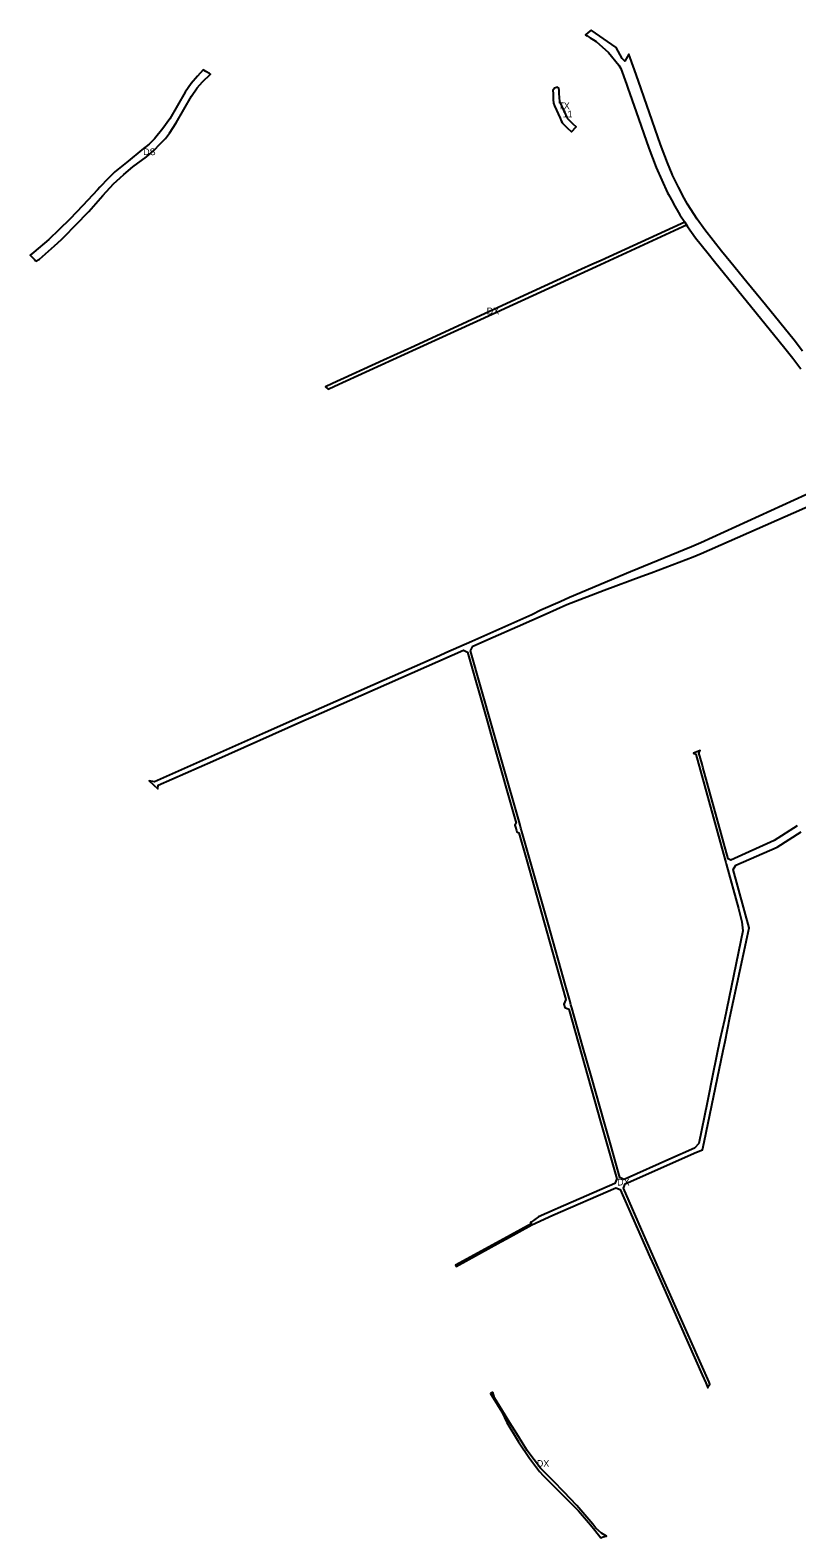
# Model space of a CAD drawing. Extents: x -521882 to -518995, y -1142400 to -1140153.
# Drawn here: x -521882 to -520739, y -1142400 to -1140153 of the extents above; entities that cross this region are included whole.
import ezdxf

# ---------------------------------------------------------------- set-up
doc = ezdxf.new("R2010")
doc.units = 0
for name, color, linetype in [('90320013', 7, 'Continuous'), ('90370013', 7, 'Continuous'), ('90440023', 7, 'Continuous'), ('ID_navrh', 7, 'Continuous')]:
    doc.layers.add(name, color=color, linetype=linetype)

msp = doc.modelspace()

# ---------------------------------------------------------------- linework, layer by layer
at = {"layer": '90320013'}
msp.add_lwpolyline([(-520730.64, -1140631.58), (-520743.28, -1140615.01), (-520785.9, -1140562.81), (-520813.81, -1140528.62), (-520837.71, -1140499.35), (-520851.49, -1140482.48), (-520876.46, -1140450.75), (-520887.82, -1140434.78), (-520902.19, -1140412.67), (-520907.24, -1140403.74), (-520915.77, -1140387.04), (-520924.44, -1140369.44), (-520925.04, -1140368.05), (-520932.27, -1140351.12), (-520942.5, -1140323.7), (-520963.03, -1140264.99), (-520975.5, -1140229.32), (-520981.4, -1140212.45), (-520989.57, -1140189.1), (-520995.82, -1140199.62), (-520997.26, -1140198.03), (-520999.73, -1140195.29), (-521008.55, -1140178.79), (-521045.99, -1140153.16), (-521047.4, -1140154.12), (-521048.05, -1140154.68), (-521053.72, -1140159.58), (-521054.36, -1140160.13), (-521051.86, -1140161.45), (-521047.19, -1140164.44), (-521042.52, -1140167.42), (-521038.45, -1140170.03), (-521019.82, -1140186.27), (-521004.56, -1140205.45), (-521002.93, -1140207.73), (-521001.72, -1140210.08), (-520993.36, -1140233.77), (-520991.34, -1140239.5), (-520978.89, -1140274.79), (-520959.74, -1140329.07), (-520948.85, -1140357.77), (-520931.92, -1140395.43), (-520930.52, -1140398.04), (-520924.28, -1140409.64), (-520923.06, -1140411.9), (-520913.58, -1140428.33), (-520906.37, -1140439.12), (-520903.84, -1140443.54), (-520902.4, -1140445.74), (-520890.58, -1140462.46), (-520871.65, -1140486.28), (-520862.22, -1140497.87), (-520765.71, -1140616.57), (-520757.18, -1140627.06), (-520745.42, -1140642.26), (-520733.42, -1140657.97)], dxfattribs=at)
msp.add_lwpolyline([(-521873.47, -1140497.6), (-521868.24, -1140494.75), (-521845.84, -1140474.71), (-521835.62, -1140465.09), (-521829.77, -1140459.58), (-521815.4, -1140444.86), (-521814.39, -1140443.83), (-521794.87, -1140423.48), (-521773.82, -1140399.6), (-521757.78, -1140381.98), (-521747.91, -1140373.33), (-521742.3, -1140368.5), (-521728.93, -1140357.06), (-521708.67, -1140341.98), (-521697.12, -1140332.11), (-521688.85, -1140323.27), (-521680.22, -1140314.66), (-521674.58, -1140306.67), (-521664.44, -1140291.34), (-521641.46, -1140251.62), (-521633.25, -1140239.25), (-521625.36, -1140230.13), (-521613.09, -1140218.9), (-521614.87, -1140217.86), (-521620.19, -1140214.77), (-521624.31, -1140212.38), (-521632.85, -1140221.77), (-521642.31, -1140232.52), (-521651.12, -1140245.38), (-521673.96, -1140285.19), (-521684.15, -1140299.89), (-521696.71, -1140315.1), (-521704.79, -1140323.18), (-521715.5, -1140331.4), (-521736.25, -1140348.4), (-521755.99, -1140364.38), (-521765.79, -1140374.26), (-521778.1, -1140387.34), (-521781.95, -1140390.97), (-521803.88, -1140414.74), (-521822.79, -1140434.86), (-521839, -1140450.48), (-521854.3, -1140465.27), (-521876.66, -1140484.09), (-521882.18, -1140488.56), (-521879.74, -1140491.09), (-521875.9, -1140495.08)], close=True, dxfattribs=at)
at = {"layer": '90370013'}
for points in [[(-520909.31, -1140446.06), (-520903.84, -1140443.54), (-520906.37, -1140439.12), (-520911.89, -1140441.66), (-521031.07, -1140496.4), (-521045.09, -1140502.65), (-521060.49, -1140509.3), (-521152, -1140551.52), (-521309.07, -1140623.96), (-521355.48, -1140644.9), (-521431.42, -1140679.77), (-521441.99, -1140684.63), (-521438.02, -1140688.47), (-521428.47, -1140683.93), (-521306.81, -1140628.37), (-521187.8, -1140573.75), (-521174.07, -1140567.72), (-521038.29, -1140505.39), (-520909.31, -1140446.06)], [(-520708.35, -1140837.86), (-520882.47, -1140917.37), (-520896.33, -1140923.45), (-520987.34, -1140960.66), (-521077.97, -1140999.02), (-521091.97, -1141005.03), (-521120.79, -1141017.67), (-521134.18, -1141024.63), (-521223.67, -1141064.26), (-521262.72, -1141081.47), (-521271.86, -1141085.49), (-521354.37, -1141121.84), (-521464.85, -1141170.68), (-521478.81, -1141176.87), (-521531.28, -1141200.09), (-521696.71, -1141273.51), (-521705, -1141272.16), (-521692.02, -1141284.07), (-521691.15, -1141278.7), (-521609.81, -1141242.59), (-521474.13, -1141182.35), (-521460.33, -1141176.23), (-521405.94, -1141152.24), (-521236.08, -1141077.32), (-521230.09, -1141080.11), (-521201.01, -1141182.77), (-521192.96, -1141211.21), (-521157.91, -1141334.94), (-521159.51, -1141338.32), (-521158.68, -1141341.24), (-521157.35, -1141345.97), (-521156.76, -1141348.04), (-521153.82, -1141349.39), (-521142.48, -1141389.44), (-521107.96, -1141511.35), (-521083.41, -1141598.05), (-521086.66, -1141604.9), (-521085.26, -1141609.76), (-521079.3, -1141612.54), (-521031.39, -1141781.75), (-521007.67, -1141865.49), (-521010.77, -1141872.32), (-521095.32, -1141908.99), (-521099.58, -1141911), (-521124.47, -1141921.72), (-521135.11, -1141929.87), (-521136.46, -1141930.46), (-521135.45, -1141932.22), (-521181.6, -1141957.64), (-521247.93, -1141994.05), (-521247.07, -1141995.86), (-521180.62, -1141959.39), (-521171.94, -1141954.7), (-521134.44, -1141933.97), (-521103.17, -1141919.44), (-521009, -1141878.54), (-521002.46, -1141881.16), (-520958.2, -1141981.43), (-520951.97, -1141995.53), (-520924.06, -1142058.74), (-520880.4, -1142157.63), (-520875.14, -1142169.56), (-520873.11, -1142174.16), (-520871.84, -1142177.03), (-520869.86, -1142172.95), (-520868.95, -1142171.08), (-520870.13, -1142168.42), (-520874.16, -1142159.29), (-520905.36, -1142088.65), (-520939.85, -1142010.61), (-520967.25, -1141948.55), (-520997.93, -1141879.1), (-520995.39, -1141872.52), (-520990.8, -1141870.5), (-520888.63, -1141825.55), (-520879.93, -1141822.22), (-520877.47, -1141810.66), (-520849.15, -1141674.02), (-520846.32, -1141660.34), (-520838.97, -1141624.77), (-520813.35, -1141504.9), (-520810.51, -1141490.93), (-520834.09, -1141404.31), (-520830.45, -1141397.51), (-520768.7, -1141371.01), (-520732.72, -1141348.25)], [(-520738.6, -1141338.95), (-520773.04, -1141360.9), (-520837.57, -1141390.54), (-520841.7, -1141388.53), (-520879.25, -1141251.61), (-520880.53, -1141246.97), (-520885.33, -1141230.38), (-520883.56, -1141226.59), (-520893.13, -1141230.74), (-520889.86, -1141232.13), (-520851.22, -1141372.34), (-520845.27, -1141393.64), (-520844.73, -1141395.54), (-520826.14, -1141462.3), (-520821.3, -1141482.16), (-520819.82, -1141495.44), (-520847.36, -1141628.04), (-520854, -1141657.98), (-520864.49, -1141709.14), (-520873.01, -1141751.95), (-520885.53, -1141812.75), (-520891.63, -1141819.53), (-520930.02, -1141836.55), (-520992.44, -1141864.11), (-520997.06, -1141866.15), (-521003.04, -1141863.38), (-521016.76, -1141814.92), (-521026.62, -1141780.12), (-521044.98, -1141715.3), (-521058.67, -1141667), (-521074.66, -1141610.52), (-521076.03, -1141605.72), (-521077.42, -1141600.82), (-521078.78, -1141596.05), (-521084.21, -1141576.91), (-521109.72, -1141486.85), (-521149.23, -1141347.36), (-521150.52, -1141342.71), (-521151.86, -1141337.89), (-521153.24, -1141332.9), (-521177.35, -1141247.92), (-521225.53, -1141078.04), (-521222.3, -1141071.25), (-521191.96, -1141057.88), (-521155.63, -1141041.85), (-521112.83, -1141022.98), (-521082.18, -1141009.47), (-521026.59, -1140987.63), (-520970.5, -1140967.09), (-520956.56, -1140961.79), (-520893.74, -1140937.98), (-520881.74, -1140933.43), (-520715.12, -1140859.45)]]:
    msp.add_lwpolyline(points, dxfattribs=at)
msp.add_lwpolyline([(-521192.34, -1142183.35), (-521195.91, -1142185.2), (-521194.57, -1142187.85), (-521178.89, -1142212.77), (-521171.39, -1142228.49), (-521154.24, -1142257.34), (-521137.94, -1142281.57), (-521123.05, -1142301.63), (-521116.76, -1142308), (-521064.97, -1142360.36), (-521046.98, -1142380.85), (-521040.41, -1142389.14), (-521031.51, -1142400.38), (-521030.42, -1142399.7), (-521028.09, -1142399.07), (-521023.14, -1142397.72), (-521030.26, -1142393.33), (-521039.1, -1142385.71), (-521043.28, -1142380.16), (-521067.07, -1142352.38), (-521086.87, -1142331.63), (-521102.18, -1142315.9), (-521121.26, -1142296.3), (-521140.11, -1142271.9), (-521141.26, -1142270.03), (-521148.58, -1142258.19), (-521154.1, -1142249.25), (-521169.79, -1142225.11), (-521174.19, -1142217.64), (-521189.97, -1142191.57)], close=True, dxfattribs=at)
at = {"layer": '90440023'}
msp.add_lwpolyline([(-521092.32, -1140284.11), (-521090.43, -1140288.34), (-521089.34, -1140290.78), (-521089.05, -1140291.44), (-521081.54, -1140298.53), (-521075.22, -1140304.5), (-521068.35, -1140297.23), (-521072.76, -1140293.07), (-521080.73, -1140285.54), (-521081.11, -1140284.7), (-521081.89, -1140282.94), (-521083.79, -1140278.7), (-521092.42, -1140259.41), (-521093.43, -1140247.58), (-521093.8, -1140243.17), (-521094.12, -1140239.48), (-521096.26, -1140238.22), (-521100.42, -1140239.62), (-521102.93, -1140242.86), (-521102.76, -1140247.73), (-521102.44, -1140256.49), (-521102.24, -1140261.94), (-521100.5, -1140265.83), (-521092.32, -1140284.11)], dxfattribs=at)

# ---------------------------------------------------------------- texts
at = {"layer": '90320013'}
msp.add_text('DS', height=10, rotation=360, dxfattribs=at).set_placement((-521713.74, -1140339.45))
at = {"layer": '90370013'}
for rotation, p in [(360, (-521201.57, -1140576.7)), (0, (-521007.23, -1141875.22)), (0, (-521126.89, -1142294.51))]:
    msp.add_text('DX', height=10, rotation=rotation, dxfattribs=at).set_placement(p)
at = {"layer": '90440023'}
msp.add_text('TX', height=10, rotation=360, dxfattribs=at).set_placement((-521094.87, -1140270.94))
at = {"layer": 'ID_navrh'}
msp.add_text('11', height=10, rotation=360, dxfattribs=at).set_placement((-521088.44, -1140283.15))

doc.saveas('drawing.dxf')
